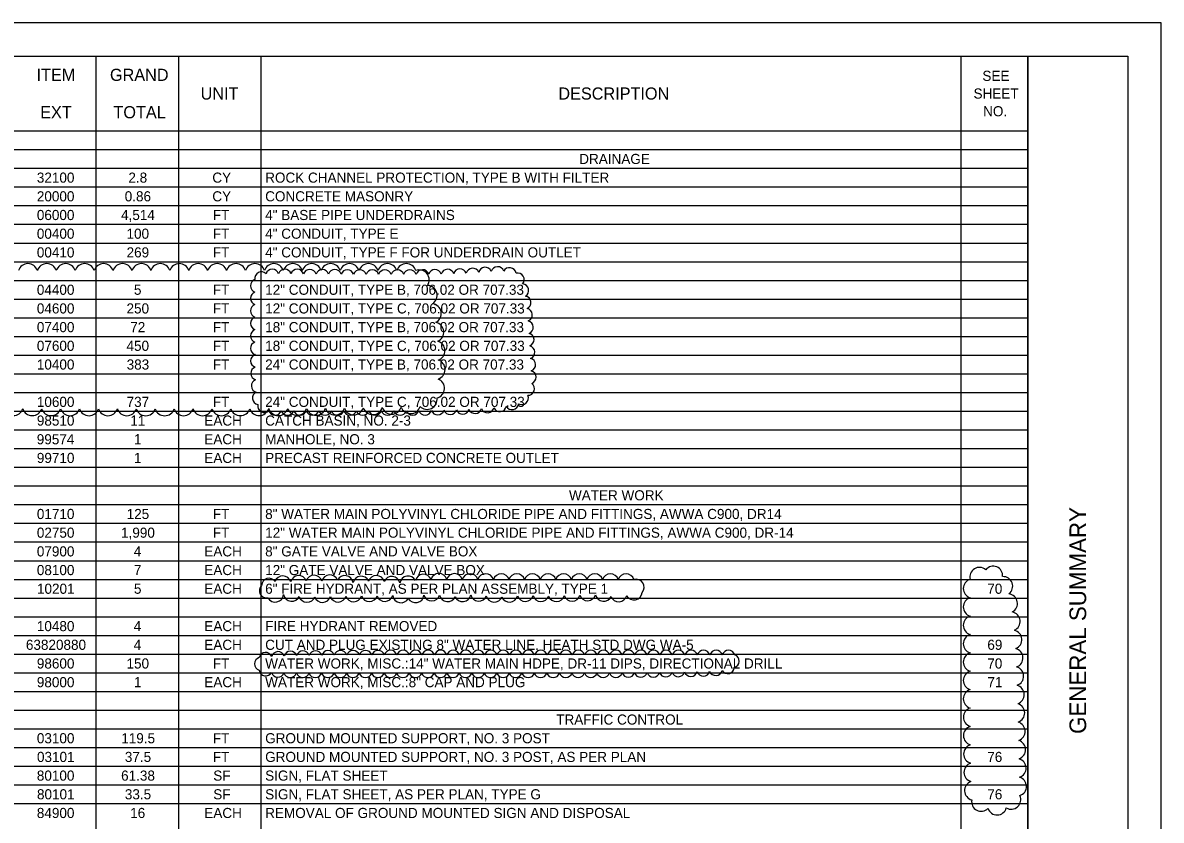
# Model space of a CAD drawing. Extents: x 0 to 36.7, y 0 to 22.
# Drawn here: x 16.94 to 34, y 10.05 to 22 of the extents above; entities that cross this region are included whole.
import ezdxf

# ---------------------------------------------------------------- set-up
doc = ezdxf.new("R2010")
doc.units = 0
for name, color, linetype in [('SC_Scratch1', 7, 'Continuous'), ('SC_Scratch2', 7, 'Continuous'), ('SH_Border', 7, 'Continuous'), ('SH_Cut_Line', 7, 'Continuous'), ('SH_Data', 7, 'Continuous'), ('SH_Text', 7, 'Continuous')]:
    doc.layers.add(name, color=color, linetype=linetype)

msp = doc.modelspace()

# ---------------------------------------------------------------- linework, layer by layer
at = {"layer": 'SC_Scratch1'}
for centre, radius, start, end in [((17.015, 18.242), 0.149, 17.5, 162.5), ((17.299, 18.242), 0.149, 17.5, 162.5), ((17.582, 18.242), 0.149, 17.5, 162.5), ((17.866, 18.242), 0.149, 17.5, 162.5), ((18.149, 18.242), 0.149, 17.5, 162.5), ((18.433, 18.242), 0.149, 17.5, 162.5), ((18.717, 18.242), 0.149, 17.5, 162.5), ((19, 18.242), 0.149, 17.5, 162.5), ((19.284, 18.242), 0.149, 17.5, 162.5), ((19.567, 18.242), 0.149, 17.5, 162.5), ((19.851, 18.242), 0.149, 17.5, 162.5), ((20.134, 18.242), 0.149, 17.5, 162.5), ((20.418, 18.242), 0.149, 17.5, 162.5), ((20.702, 18.242), 0.149, 17.5, 162.5), ((20.985, 18.242), 0.149, 17.5, 162.5), ((21.269, 18.242), 0.149, 17.5, 162.5), ((21.552, 18.242), 0.149, 17.5, 162.5), ((21.836, 18.242), 0.149, 17.5, 162.5), ((22.119, 18.242), 0.149, 17.5, 162.5), ((22.403, 18.242), 0.149, 17.5, 162.5), ((22.686, 18.242), 0.149, 17.5, 162.5), ((22.881, 18.147), 0.149, 325.7665, 110.7665), ((22.999, 17.915), 0.149, 303.0651, 88.0651), ((23.061, 17.643), 0.149, 297.7389, 82.7389), ((23.099, 17.366), 0.149, 292.8393, 77.8393), ((23.116, 17.086), 0.149, 289.225, 74.225), ((23.119, 16.805), 0.149, 286.9548, 71.9548), ((23.11, 16.523), 0.149, 284.216, 69.216), ((16.796, 16.263), 0.149, 197.3692, 342.3692), ((17.08, 16.262), 0.149, 197.3872, 342.3872), ((17.363, 16.262), 0.149, 197.4049, 342.4049), ((17.647, 16.261), 0.149, 197.4223, 342.4223), ((17.931, 16.261), 0.149, 197.4394, 342.4394), ((18.214, 16.261), 0.149, 197.4563, 342.4563), ((18.498, 16.261), 0.149, 197.4729, 342.4729), ((18.781, 16.26), 0.149, 197.4892, 342.4892), ((19.065, 16.26), 0.149, 197.5104, 342.5104), ((19.348, 16.261), 0.149, 197.543, 342.543), ((19.632, 16.261), 0.149, 197.5796, 342.5796), ((19.915, 16.261), 0.149, 197.6211, 342.6211), ((20.199, 16.262), 0.149, 197.6684, 342.6684), ((20.482, 16.263), 0.149, 197.7232, 342.7232), ((20.766, 16.264), 0.149, 197.7877, 342.7877), ((21.049, 16.266), 0.149, 197.865, 342.865), ((21.333, 16.268), 0.149, 197.9601, 342.9601), ((21.616, 16.271), 0.149, 198.0811, 343.0811), ((21.9, 16.274), 0.149, 198.2423, 343.2423), ((22.183, 16.278), 0.149, 198.473, 343.473), ((22.466, 16.284), 0.149, 198.8441, 343.8441), ((22.749, 16.292), 0.149, 199.6107, 344.6107), ((22.999, 16.356), 0.149, 223.9632, 8.9632), ((20.628, 13.567), 0.11, 33.9293, 178.9293), ((20.836, 13.589), 0.123, 16.6725, 161.6725), ((21.072, 13.594), 0.123, 20.6515, 165.6515), ((21.303, 13.599), 0.123, 16.6725, 161.6725), ((21.54, 13.605), 0.123, 21.3885, 166.3885), ((21.765, 13.593), 0.124, 7.8725, 152.8725), ((22.009, 13.585), 0.123, 22.9361, 167.9361), ((22.238, 13.594), 0.123, 16.719, 161.719), ((22.469, 13.581), 0.123, 11.6695, 156.6695), ((22.712, 13.586), 0.124, 26.1443, 171.1443), ((22.943, 13.614), 0.123, 22.4883, 167.4883), ((23.174, 13.624), 0.123, 17.2135, 162.2135), ((23.407, 13.623), 0.123, 17.2728, 162.2728), ((23.641, 13.622), 0.123, 17.3277, 162.3277), ((23.875, 13.622), 0.123, 17.3787, 162.3787), ((24.109, 13.621), 0.123, 17.4261, 162.4261), ((24.342, 13.621), 0.123, 17.4705, 162.4705), ((24.576, 13.621), 0.123, 17.4992, 162.4992), ((24.81, 13.621), 0.123, 17.5, 162.5), ((25.044, 13.621), 0.123, 17.5, 162.5), ((25.278, 13.621), 0.123, 17.5, 162.5), ((25.511, 13.621), 0.123, 17.5, 162.5), ((25.745, 13.621), 0.123, 17.5, 162.5), ((25.979, 13.621), 0.123, 17.5, 162.5), ((26.129, 13.541), 0.121, 320.6115, 105.6115), ((20.595, 13.49), 0.11, 134.2606, 279.2606), ((20.722, 13.444), 0.125, 209.4557, 354.4557), ((20.968, 13.455), 0.123, 190.8826, 335.8826), ((21.198, 13.439), 0.123, 196.2618, 341.2618), ((21.431, 13.438), 0.123, 198.1686, 343.1686), ((21.664, 13.443), 0.123, 199.3566, 344.3566), ((21.898, 13.448), 0.123, 198.298, 343.298), ((22.132, 13.45), 0.123, 197.7672, 342.7672), ((22.365, 13.453), 0.123, 198.3445, 343.3445), ((22.606, 13.433), 0.124, 187.3354, 332.3354), ((22.826, 13.435), 0.125, 208.6995, 353.6995), ((23.067, 13.46), 0.123, 198.3796, 343.3796), ((23.305, 13.45), 0.123, 191.7159, 336.7159), ((23.531, 13.451), 0.123, 203.4659, 348.4659), ((23.77, 13.457), 0.123, 194.6197, 339.6197), ((24.005, 13.443), 0.123, 193.3519, 338.3519), ((24.233, 13.442), 0.123, 201.4964, 346.4964), ((24.469, 13.453), 0.123, 198.5903, 343.5903), ((24.704, 13.451), 0.123, 195.6959, 340.6959), ((24.936, 13.45), 0.123, 198.8158, 343.8158), ((25.17, 13.456), 0.123, 198.9778, 343.9778), ((25.403, 13.463), 0.123, 199.1994, 344.1994), ((25.642, 13.454), 0.123, 191.6917, 336.6917), ((25.87, 13.448), 0.123, 200.1046, 345.1046), ((26.097, 13.477), 0.125, 209.3042, 354.3042)]:
    msp.add_arc(centre, radius, start, end, dxfattribs=at)
at = {"layer": 'SC_Scratch2'}
for centre, radius, start, end in [((20.515, 18.17), 0.0983, 45.5733, 190.5733), ((20.677, 18.21), 0.0983, 17.0915, 162.0915), ((20.864, 18.209), 0.0983, 17.0915, 162.0915), ((21.052, 18.208), 0.0983, 17.0915, 162.0915), ((21.24, 18.206), 0.0983, 17.0915, 162.0915), ((21.427, 18.205), 0.0983, 17.0915, 162.0915), ((21.615, 18.204), 0.0983, 17.0915, 162.0915), ((21.802, 18.202), 0.0983, 17.0915, 162.0915), ((21.99, 18.201), 0.0983, 17.1441, 162.1441), ((22.177, 18.2), 0.0983, 17.2665, 162.2665), ((22.365, 18.2), 0.0983, 17.4103, 162.4103), ((22.553, 18.2), 0.0983, 17.5826, 162.5826), ((22.74, 18.2), 0.0983, 17.7941, 162.7941), ((22.928, 18.202), 0.0983, 18.0625, 163.0625), ((23.116, 18.204), 0.0983, 18.4191, 163.4191), ((23.304, 18.208), 0.0983, 18.9263, 163.9263), ((23.491, 18.214), 0.0983, 19.7341, 164.7341), ((23.68, 18.224), 0.0983, 21.3583, 166.3583), ((23.867, 18.238), 0.0983, 22.1339, 167.1339), ((24.052, 18.247), 0.0983, 18.2448, 163.2448), ((24.233, 18.233), 0.0983, 8.2615, 153.2615), ((20.448, 18.059), 0.0983, 107.5, 252.5), ((24.355, 18.152), 0.0984, 319.5841, 104.5841), ((24.422, 17.99), 0.0983, 300.2218, 85.2218), ((20.448, 17.871), 0.0983, 107.5, 252.5), ((20.448, 17.684), 0.0983, 107.5, 252.5), ((24.455, 17.808), 0.0983, 295.2235, 80.2235), ((20.448, 17.496), 0.0983, 107.5, 252.5), ((24.476, 17.623), 0.0983, 292.6625, 77.6625), ((24.49, 17.437), 0.0983, 291.2847, 76.2847), ((20.448, 17.308), 0.0983, 107.5, 252.5), ((24.502, 17.25), 0.0983, 291.0875, 76.0875), ((20.448, 17.121), 0.0983, 107.7419, 252.7419), ((24.514, 17.063), 0.0983, 290.9244, 75.9244), ((20.45, 16.934), 0.0983, 108.3445, 253.3445), ((24.525, 16.876), 0.0983, 290.6181, 75.6181), ((20.454, 16.747), 0.0983, 109.234, 254.234), ((24.533, 16.689), 0.0983, 289.4249, 74.4249), ((20.462, 16.56), 0.0983, 110.7505, 255.7505), ((24.508, 16.516), 0.0983, 269.5058, 54.5058), ((20.478, 16.375), 0.0983, 114.4123, 259.4123), ((24.418, 16.376), 0.0983, 239.9732, 24.9732), ((20.557, 16.259), 0.0983, 168.4018, 313.4018), ((23.717, 16.243), 0.0983, 200.5796, 345.5796), ((23.903, 16.255), 0.0983, 201.8246, 346.8246), ((24.089, 16.272), 0.0983, 203.9524, 348.9524), ((24.271, 16.301), 0.0983, 209.0907, 354.0907), ((20.718, 16.217), 0.0983, 197.5, 342.5), ((20.906, 16.217), 0.0983, 197.5, 342.5), ((21.093, 16.217), 0.0983, 197.5, 342.5), ((21.281, 16.217), 0.0983, 197.5, 342.5), ((21.468, 16.217), 0.0983, 197.5, 342.5), ((21.656, 16.217), 0.0983, 197.5, 342.5), ((21.843, 16.217), 0.0983, 197.5, 342.5), ((22.031, 16.217), 0.0983, 197.5, 342.5), ((22.218, 16.217), 0.0983, 197.5, 342.5), ((22.406, 16.217), 0.0983, 197.5051, 342.5051), ((22.593, 16.217), 0.0983, 197.6692, 342.6692), ((22.781, 16.218), 0.0983, 197.9379, 342.9379), ((22.968, 16.22), 0.0983, 198.2559, 343.2559), ((23.156, 16.223), 0.0983, 198.6407, 343.6407), ((23.343, 16.228), 0.0983, 199.1194, 344.1194), ((23.53, 16.234), 0.0983, 199.7375, 344.7375), ((31.275, 13.696), 0.144, 49.286, 194.286), ((31.48, 13.713), 0.144, 355.1869, 140.1869), ((31.178, 13.523), 0.144, 107.5, 252.5), ((31.63, 13.557), 0.144, 307.5186, 92.5186), ((31.178, 13.247), 0.144, 107.5, 252.5), ((31.701, 13.299), 0.144, 298.065, 83.065), ((31.741, 13.03), 0.144, 294.0806, 79.0806), ((31.178, 12.972), 0.144, 107.5, 252.5), ((31.178, 12.696), 0.144, 107.5, 252.5), ((31.767, 12.757), 0.144, 291.7623, 76.7623), ((20.511, 12.394), 0.0983, 107.4222, 252.4222), ((20.578, 12.467), 0.0984, 22.58, 167.58), ((20.764, 12.479), 0.0984, 19.7924, 164.7924), ((20.951, 12.485), 0.0984, 18.9918, 163.9918), ((21.138, 12.489), 0.0984, 18.5604, 163.5604), ((21.325, 12.492), 0.0984, 18.2797, 163.2797), ((21.513, 12.494), 0.0984, 18.0782, 163.0782), ((21.7, 12.496), 0.0984, 17.9246, 162.9246), ((21.888, 12.497), 0.0984, 17.8023, 162.8023), ((22.076, 12.498), 0.0984, 17.7021, 162.7021), ((22.263, 12.498), 0.0984, 17.6179, 162.6179), ((22.451, 12.499), 0.0984, 17.5459, 162.5459), ((22.638, 12.499), 0.0984, 17.5014, 162.5014), ((22.826, 12.499), 0.0984, 17.5, 162.5), ((23.014, 12.499), 0.0984, 17.5, 162.5), ((23.201, 12.499), 0.0984, 17.5, 162.5), ((23.389, 12.499), 0.0984, 17.5, 162.5), ((23.576, 12.499), 0.0984, 17.5, 162.5), ((23.764, 12.499), 0.0984, 17.5, 162.5), ((23.952, 12.499), 0.0984, 17.5, 162.5), ((24.139, 12.499), 0.0984, 17.5, 162.5), ((24.327, 12.499), 0.0984, 17.5, 162.5), ((24.515, 12.499), 0.0984, 17.5, 162.5), ((24.702, 12.499), 0.0984, 17.5, 162.5), ((24.89, 12.499), 0.0984, 17.5, 162.5), ((25.077, 12.499), 0.0984, 17.5, 162.5), ((25.265, 12.499), 0.0984, 17.5, 162.5), ((25.453, 12.499), 0.0984, 17.5, 162.5), ((25.64, 12.499), 0.0984, 17.5, 162.5), ((25.828, 12.499), 0.0984, 17.5, 162.5), ((26.015, 12.499), 0.0984, 17.5, 162.5), ((26.203, 12.499), 0.0984, 17.5, 162.5), ((26.391, 12.499), 0.0984, 17.5, 162.5), ((26.578, 12.499), 0.0984, 17.5, 162.5), ((26.766, 12.499), 0.0984, 17.5, 162.5), ((26.954, 12.499), 0.0984, 17.5, 162.5), ((27.141, 12.499), 0.0984, 17.5, 162.5), ((27.329, 12.499), 0.0984, 17.5, 162.5), ((27.516, 12.499), 0.0984, 17.5, 162.5), ((27.576, 12.436), 0.0984, 284.6089, 69.6089), ((31.178, 12.421), 0.144, 107.5, 252.5), ((31.784, 12.484), 0.144, 290.204, 75.204), ((20.579, 12.312), 0.0984, 186.5456, 331.5456), ((27.324, 12.318), 0.0984, 200.527, 345.527), ((27.503, 12.346), 0.0984, 212.3442, 357.3442), ((31.794, 12.209), 0.144, 289.1879, 74.1879), ((20.76, 12.292), 0.0984, 195.9532, 340.9532), ((20.947, 12.288), 0.0984, 196.8567, 341.8567), ((21.135, 12.287), 0.0984, 197.2913, 342.2913), ((21.322, 12.286), 0.0984, 197.4938, 342.4938), ((21.51, 12.286), 0.0984, 197.5, 342.5), ((21.698, 12.286), 0.0984, 197.5, 342.5), ((21.885, 12.286), 0.0984, 197.5, 342.5), ((22.073, 12.286), 0.0984, 197.5, 342.5), ((22.26, 12.286), 0.0984, 197.5, 342.5), ((22.448, 12.286), 0.0984, 197.5, 342.5), ((22.636, 12.286), 0.0984, 197.5, 342.5), ((22.823, 12.286), 0.0984, 197.5, 342.5), ((23.011, 12.286), 0.0984, 197.5, 342.5), ((23.198, 12.286), 0.0984, 197.5, 342.5), ((23.386, 12.286), 0.0984, 197.5, 342.5), ((23.574, 12.286), 0.0984, 197.5, 342.5), ((23.761, 12.286), 0.0984, 197.5, 342.5), ((23.949, 12.286), 0.0984, 197.5, 342.5), ((24.137, 12.286), 0.0984, 197.5, 342.5), ((24.324, 12.286), 0.0984, 197.5, 342.5), ((24.512, 12.286), 0.0984, 197.5, 342.5), ((24.699, 12.286), 0.0984, 197.5029, 342.5029), ((24.887, 12.286), 0.0984, 197.5372, 342.5372), ((25.075, 12.287), 0.0984, 197.5839, 342.5839), ((25.262, 12.287), 0.0984, 197.6362, 342.6362), ((25.45, 12.288), 0.0984, 197.6953, 342.6953), ((25.637, 12.288), 0.0984, 197.7628, 342.7628), ((25.825, 12.289), 0.0984, 197.8409, 342.8409), ((26.013, 12.291), 0.0984, 197.9327, 342.9327), ((26.2, 12.292), 0.0984, 198.0429, 343.0429), ((26.388, 12.294), 0.0984, 198.1784, 343.1784), ((26.575, 12.297), 0.0984, 198.3508, 343.3508), ((26.763, 12.3), 0.0984, 198.5806, 343.5806), ((26.95, 12.304), 0.0984, 198.9091, 343.9091), ((27.137, 12.309), 0.0984, 199.4375, 344.4375), ((31.178, 12.146), 0.144, 107.5, 252.5), ((31.178, 11.87), 0.144, 107.5627, 252.5627), ((31.802, 11.934), 0.144, 289.0498, 74.0498), ((31.81, 11.658), 0.144, 289.0276, 74.0276), ((31.179, 11.595), 0.144, 107.7128, 252.7128), ((31.181, 11.319), 0.144, 107.9172, 252.9172), ((31.817, 11.383), 0.144, 288.9966, 73.9966), ((31.183, 11.044), 0.144, 108.2193, 253.2193), ((31.824, 11.108), 0.144, 288.9489, 73.9489), ((31.831, 10.832), 0.144, 288.8603, 73.8603), ((31.188, 10.769), 0.144, 108.737, 253.737), ((31.197, 10.495), 0.144, 110.0146, 255.0146), ((31.836, 10.557), 0.144, 288.5444, 73.5444), ((31.751, 10.36), 0.144, 239.7874, 24.7874), ((31.302, 10.329), 0.144, 169.6929, 314.6929), ((31.54, 10.274), 0.144, 199.1877, 344.1877)]:
    msp.add_arc(centre, radius, start, end, dxfattribs=at)
at = {"layer": 'SH_Border'}
msp.add_line((32, 0.5), (32, 21.5), dxfattribs=at)
msp.add_lwpolyline([(1.5, 21.5), (33.5, 21.5), (33.5, 0.5), (1.5, 0.5)], close=True, dxfattribs=at)
at = {"layer": 'SH_Cut_Line'}
msp.add_lwpolyline([(0, 0), (34, 0), (34, 22), (0, 22)], close=True, dxfattribs=at)
at = {"layer": 'SH_Text'}
for p, q in [((1.5, 21.5), (32, 21.5)), ((18.035, 21.5), (18.035, 0.5)), ((19.27, 21.5), (19.27, 0.5)), ((20.505, 21.5), (20.505, 0.5)), ((30.995, 21.5), (30.995, 0.5)), ((32, 21.5), (32, 0.5)), ((1.5, 20.38), (32, 20.38)), ((1.5, 20.1), (32, 20.1)), ((1.5, 19.82), (32, 19.82)), ((1.5, 19.54), (32, 19.54)), ((1.5, 19.26), (32, 19.26)), ((1.5, 18.98), (32, 18.98)), ((1.5, 18.7), (32, 18.7)), ((1.5, 18.42), (32, 18.42)), ((1.5, 18.14), (32, 18.14)), ((1.5, 17.86), (32, 17.86)), ((1.5, 17.58), (32, 17.58)), ((1.5, 17.3), (32, 17.3)), ((1.5, 17.02), (32, 17.02)), ((1.5, 16.74), (32, 16.74)), ((1.5, 16.46), (32, 16.46)), ((1.5, 16.18), (32, 16.18)), ((1.5, 15.9), (32, 15.9)), ((1.5, 15.62), (32, 15.62)), ((1.5, 15.34), (32, 15.34)), ((1.5, 15.06), (32, 15.06)), ((1.5, 14.78), (32, 14.78)), ((1.5, 14.5), (32, 14.5)), ((1.5, 14.22), (32, 14.22)), ((1.5, 13.94), (32, 13.94)), ((1.5, 13.66), (32, 13.66)), ((1.5, 13.38), (32, 13.38)), ((1.5, 13.1), (32, 13.1)), ((1.5, 12.82), (32, 12.82)), ((1.5, 12.54), (32, 12.54)), ((1.5, 12.26), (32, 12.26)), ((1.5, 11.98), (32, 11.98)), ((1.5, 11.7), (32, 11.7)), ((1.5, 11.42), (32, 11.42)), ((1.5, 11.14), (32, 11.14)), ((1.5, 10.86), (32, 10.86)), ((1.5, 10.58), (32, 10.58)), ((1.5, 10.3), (32, 10.3))]:
    msp.add_line(p, q, dxfattribs=at)

# ---------------------------------------------------------------- texts
at = {"layer": 'SH_Data'}
msp.add_text('GENERAL SUMMARY', height=0.25, rotation=90, dxfattribs=at).set_placement((32.875, 11.344))
at = {"layer": 'SH_Text'}
for s, height, p in [('ITEM', 0.1818, (17.145, 21.129)), ('GRAND', 0.1818, (18.245, 21.129)), ('SEE ', 0.1515, (31.32, 21.129)), ('UNIT', 0.1818, (19.604, 20.849)), ('DESCRIPTION', 0.18184, (24.965, 20.849)), ('SHEET ', 0.1515, (31.187, 20.864)), ('EXT', 0.1818, (17.199, 20.569)), ('TOTAL', 0.1818, (18.297, 20.569)), ('NO.', 0.1515, (31.331, 20.599)), ('DRAINAGE', 0.1515, (25.278, 19.884)), ('32100', 0.1515, (17.149, 19.604)), ('2.8', 0.1515, (18.521, 19.604)), ('CY', 0.1515, (19.779, 19.604)), ('ROCK CHANNEL PROTECTION, TYPE B WITH FILTER', 0.15153, (20.571, 19.604)), ('20000', 0.1515, (17.149, 19.324)), ('0.86', 0.1515, (18.466, 19.324)), ('CY', 0.1515, (19.779, 19.324)), ('CONCRETE MASONRY', 0.15153, (20.571, 19.324)), ('06000', 0.1515, (17.149, 19.044)), ('4,514', 0.1515, (18.411, 19.044)), ('FT', 0.1515, (19.786, 19.044)), ('4" BASE PIPE UNDERDRAINS', 0.15153, (20.571, 19.044)), ('00400', 0.1515, (17.149, 18.764)), ('100', 0.1515, (18.493, 18.764)), ('FT', 0.1515, (19.786, 18.764)), ('4" CONDUIT, TYPE E', 0.15153, (20.571, 18.764)), ('00410', 0.1515, (17.149, 18.484)), ('269', 0.1515, (18.494, 18.484)), ('FT', 0.1515, (19.786, 18.484)), ('4" CONDUIT, TYPE F FOR UNDERDRAIN OUTLET', 0.15153, (20.571, 18.484)), ('04400', 0.1515, (17.149, 17.924)), ('5', 0.152, (18.604, 17.924)), ('FT', 0.1515, (19.786, 17.924)), ('12" CONDUIT, TYPE B, 706.02 OR 707.33', 0.15153, (20.571, 17.924)), ('04600', 0.1515, (17.149, 17.644)), ('250', 0.1515, (18.493, 17.644)), ('FT', 0.1515, (19.786, 17.644)), ('12" CONDUIT, TYPE C, 706.02 OR 707.33', 0.15153, (20.571, 17.644)), ('07400', 0.1515, (17.149, 17.364)), ('72', 0.1515, (18.549, 17.364)), ('FT', 0.1515, (19.786, 17.364)), ('18" CONDUIT, TYPE B, 706.02 OR 707.33', 0.15153, (20.571, 17.364)), ('07600', 0.1515, (17.149, 17.084)), ('450', 0.1515, (18.493, 17.084)), ('FT', 0.1515, (19.786, 17.084)), ('18" CONDUIT, TYPE C, 706.02 OR 707.33', 0.15153, (20.571, 17.084)), ('10400', 0.1515, (17.149, 16.804)), ('383', 0.1515, (18.495, 16.804)), ('FT', 0.1515, (19.786, 16.804)), ('24" CONDUIT, TYPE B, 706.02 OR 707.33', 0.15153, (20.571, 16.804)), ('10600', 0.1515, (17.149, 16.244)), ('737', 0.1515, (18.494, 16.244)), ('FT', 0.1515, (19.786, 16.244)), ('24" CONDUIT, TYPE C, 706.02 OR 707.33', 0.15153, (20.571, 16.244)), ('98510', 0.1515, (17.149, 15.964)), ('11', 0.1515, (18.549, 15.964)), ('EACH', 0.1515, (19.659, 15.964)), ('CATCH BASIN, NO. 2-3', 0.15153, (20.571, 15.964)), ('99574', 0.1515, (17.148, 15.684)), ('1', 0.152, (18.604, 15.684)), ('EACH', 0.1515, (19.659, 15.684)), ('MANHOLE, NO. 3', 0.15153, (20.571, 15.684)), ('99710', 0.1515, (17.149, 15.404)), ('1', 0.152, (18.604, 15.404)), ('EACH', 0.1515, (19.659, 15.404)), ('PRECAST REINFORCED CONCRETE OUTLET', 0.15153, (20.571, 15.404)), ('WATER WORK', 0.1515, (25.124, 14.844)), ('01710', 0.1515, (17.149, 14.564)), ('125', 0.1515, (18.495, 14.564)), ('FT', 0.1515, (19.786, 14.564)), ('8" WATER MAIN POLYVINYL CHLORIDE PIPE AND FITTINGS, AWWA C900, DR14', 0.15153, (20.571, 14.564)), ('02750', 0.1515, (17.149, 14.284)), ('1,990', 0.1515, (18.411, 14.284)), ('FT', 0.1515, (19.786, 14.284)), ('12" WATER MAIN POLYVINYL CHLORIDE PIPE AND FITTINGS, AWWA C900, DR-14', 0.15153, (20.571, 14.284)), ('07900', 0.1515, (17.149, 14.004)), ('4', 0.152, (18.601, 14.004)), ('EACH', 0.1515, (19.659, 14.004)), ('8" GATE VALVE AND VALVE BOX', 0.15153, (20.571, 14.004)), ('08100', 0.1515, (17.149, 13.724)), ('7', 0.152, (18.603, 13.724)), ('EACH', 0.1515, (19.659, 13.724)), ('12" GATE VALVE AND VALVE BOX', 0.15153, (20.571, 13.724)), ('10201', 0.1515, (17.151, 13.444)), ('5', 0.152, (18.604, 13.444)), ('EACH', 0.1515, (19.659, 13.444)), ('6" FIRE HYDRANT, AS PER PLAN ASSEMBLY, TYPE 1', 0.15153, (20.571, 13.444)), ('70', 0.1515, (31.393, 13.444)), ('10480', 0.1515, (17.149, 12.884)), ('4', 0.152, (18.601, 12.884)), ('EACH', 0.1515, (19.659, 12.884)), ('FIRE HYDRANT REMOVED', 0.15153, (20.571, 12.884)), ('63820880', 0.1515, (16.985, 12.604)), ('4', 0.152, (18.601, 12.604)), ('EACH', 0.1515, (19.659, 12.604)), ('CUT AND PLUG EXISTING 8" WATER LINE, HEATH STD DWG WA-5', 0.15153, (20.571, 12.604)), ('69', 0.1515, (31.394, 12.604)), ('98600', 0.1515, (17.149, 12.324)), ('150', 0.1515, (18.493, 12.324)), ('FT', 0.1515, (19.786, 12.324)), ('WATER WORK, MISC.:14" WATER MAIN HDPE, DR-11 DIPS, DIRECTIONAL DRILL', 0.15153, (20.571, 12.324)), ('70', 0.1515, (31.393, 12.324)), ('98000', 0.1515, (17.149, 12.044)), ('1', 0.152, (18.604, 12.044)), ('EACH', 0.1515, (19.659, 12.044)), ('WATER WORK, MISC.:8" CAP AND PLUG', 0.15153, (20.571, 12.044)), ('71', 0.1515, (31.395, 12.044)), ('TRAFFIC CONTROL', 0.15153, (24.933, 11.484)), ('03100', 0.1515, (17.149, 11.204)), ('119.5', 0.1515, (18.414, 11.204)), ('FT', 0.1515, (19.786, 11.204)), ('GROUND MOUNTED SUPPORT, NO. 3 POST', 0.15153, (20.571, 11.204)), ('03101', 0.1515, (17.151, 10.924)), ('37.5', 0.1515, (18.468, 10.924)), ('FT', 0.1515, (19.786, 10.924)), ('GROUND MOUNTED SUPPORT, NO. 3 POST, AS PER PLAN', 0.15153, (20.571, 10.924)), ('76', 0.1515, (31.393, 10.924)), ('80100', 0.1515, (17.149, 10.644)), ('61.38', 0.1515, (18.412, 10.644)), ('SF', 0.1515, (19.793, 10.644)), ('SIGN, FLAT SHEET', 0.15153, (20.571, 10.644)), ('80101', 0.1515, (17.151, 10.364)), ('33.5', 0.1515, (18.468, 10.364)), ('SF', 0.1515, (19.793, 10.364)), ('SIGN, FLAT SHEET, AS PER PLAN, TYPE G', 0.15153, (20.571, 10.364)), ('76', 0.1515, (31.393, 10.364)), ('84900', 0.1515, (17.149, 10.084)), ('16', 0.1515, (18.548, 10.084)), ('EACH', 0.1515, (19.659, 10.084)), ('REMOVAL OF GROUND MOUNTED SIGN AND DISPOSAL', 0.15153, (20.571, 10.084))]:
    msp.add_text(s, height=height, dxfattribs=at).set_placement(p)

doc.saveas('drawing.dxf')
